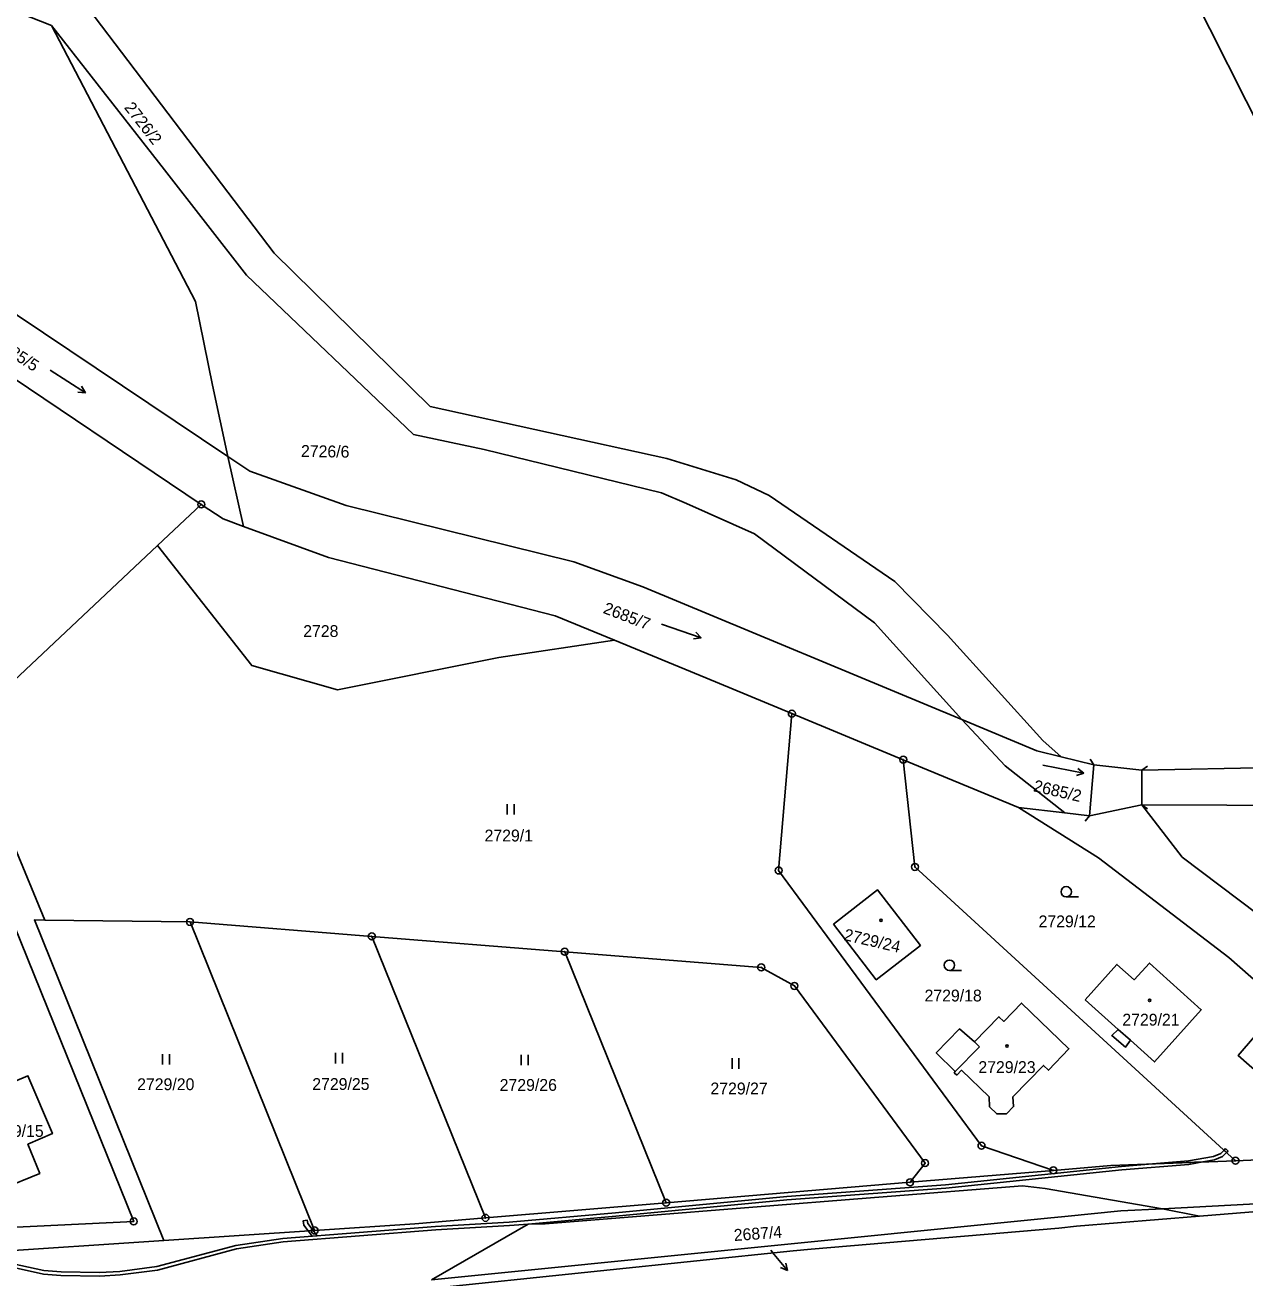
# Model space of a CAD drawing. Extents: x -562167 to -556918, y -1077891 to -1070763.
# Drawn here: x -561602.8 to -561427.7, y -1076310.6 to -1076130.7 of the extents above; entities that cross this region are included whole.
import ezdxf

# ---------------------------------------------------------------- set-up
doc = ezdxf.new("R2010")
doc.units = 0
for name, color, linetype in [('Hranice parcel', 7, 'Continuous'), ('Parcelní čísla', 7, 'Continuous'), ('Pop  PČ popisy', 7, 'Continuous'), ('Vnitřní kresba', 7, 'Continuous'), ('Věcná břemena k části', 7, 'Continuous'), ('Značky bodu BP', 7, 'Continuous'), ('Značky budov', 7, 'Continuous'), ('Značky kultur', 7, 'Continuous')]:
    doc.layers.add(name, color=color, linetype=linetype)

msp = doc.modelspace()

# ---------------------------------------------------------------- linework, layer by layer
at = {"layer": 'Hranice parcel'}
for p, q in [((-561571.48, -1076202.71), (-561573.75, -1076192.66)), ((-561577.54, -1076199.54), (-561583.82, -1076205.45)), ((-561611.5, -1076231.49), (-561583.82, -1076205.45)), ((-561492.75, -1076229.57), (-561494.65, -1076252.1)), ((-561476.76, -1076236.19), (-561492.75, -1076229.57)), ((-561611.5, -1076231.49), (-561599.99, -1076259.22)), ((-561460.21, -1076243.05), (-561476.76, -1076236.19)), ((-561449.38, -1076236.95), (-561454.1, -1076235.78)), ((-561449.38, -1076236.95), (-561450, -1076244.24)), ((-561449.38, -1076236.95), (-561442.49, -1076237.7)), ((-561442.49, -1076237.7), (-561375.18, -1076236.27)), ((-561453.54, -1076243.83), (-561460.21, -1076243.05)), ((-561450, -1076244.24), (-561453.54, -1076243.83)), ((-561442.52, -1076242.68), (-561450, -1076244.24)), ((-561494.65, -1076252.1), (-561465.52, -1076291.6)), ((-561599.99, -1076259.22), (-561579.16, -1076259.48)), ((-561579.16, -1076259.48), (-561553.06, -1076261.56)), ((-561561.27, -1076303.77), (-561579.16, -1076259.48)), ((-561553.06, -1076261.56), (-561525.36, -1076263.76)), ((-561536.74, -1076301.96), (-561553.06, -1076261.56)), ((-561510.8, -1076299.79), (-561525.36, -1076263.76)), ((-561465.52, -1076291.6), (-561455.2, -1076295.14)), ((-561429.05, -1076293.76), (-561402.88, -1076292.75)), ((-561473.63, -1076294.09), (-561475.77, -1076296.86)), ((-561475.77, -1076296.86), (-561455.2, -1076295.14)), ((-561475.77, -1076296.86), (-561510.8, -1076299.79)), ((-561510.8, -1076299.79), (-561536.74, -1076301.96)), ((-561434.2, -1076301.72), (-561451.88, -1076303.16)), ((-561439.54, -1076300.66), (-561434.2, -1076301.72)), ((-561412.9, -1076299.98), (-561434.2, -1076301.72)), ((-561561.27, -1076303.77), (-561582.91, -1076305.21)), ((-561520.21, -1076309.57), (-561546.88, -1076312.35))]:
    msp.add_line(p, q, dxfattribs=at)
for points in [[(-561375.18, -1076236.27), (-561404.09, -1076188.07), (-561456.17, -1076084.78), (-561492.73, -1076003.82), (-561505.41, -1075975.77), (-561525.58, -1075948.34), (-561553.58, -1075909.05)], [(-561454.1, -1076235.78), (-561456.7, -1076233.45), (-561470.39, -1076218.31), (-561477.97, -1076210.6), (-561496.01, -1076198.25), (-561500.73, -1076196.01), (-561510.72, -1076192.96), (-561544.7, -1076185.49), (-561567.06, -1076163.49), (-561595.66, -1076125.84), (-561602.88, -1076123.5), (-561630.58, -1076112.06), (-561664.84, -1076098.05), (-561685.79, -1076089.54), (-561702.62, -1076082.16), (-561707.57, -1076079.44)], [(-561703.43, -1076087.04), (-561686.65, -1076094.27), (-561665.16, -1076103.09), (-561628.85, -1076118.6), (-561608.1, -1076127.25), (-561599.04, -1076130.81)], [(-561599.04, -1076130.81), (-561582.81, -1076151.5), (-561571.03, -1076166.62), (-561547.05, -1076189.5), (-561536.95, -1076191.66), (-561511.46, -1076197.88), (-561507.86, -1076199.43), (-561498.09, -1076203.78), (-561480.9, -1076216.53), (-561468.34, -1076230.44)], [(-561599.04, -1076130.81), (-561578.36, -1076170.43), (-561575.95, -1076182.41), (-561573.75, -1076192.66)], [(-561573.75, -1076192.66), (-561603.99, -1076172.38), (-561621.59, -1076159.92)], [(-561577.54, -1076199.54), (-561609.14, -1076178.33), (-561619.66, -1076170.1)], [(-561468.34, -1076230.44), (-561514.16, -1076211.36), (-561524.03, -1076207.79), (-561556.75, -1076199.71), (-561570.59, -1076194.78), (-561573.75, -1076192.66)], [(-561571.48, -1076202.71), (-561574.41, -1076201.64), (-561577.54, -1076199.54)], [(-561518.21, -1076219.03), (-561526.71, -1076215.56), (-561559.3, -1076207.17), (-561571.48, -1076202.71)], [(-561583.82, -1076205.45), (-561570.29, -1076222.68), (-561557.97, -1076226.14), (-561534.8, -1076221.5), (-561518.21, -1076219.03)], [(-561492.75, -1076229.57), (-561505.12, -1076224.46), (-561518.21, -1076219.03)], [(-561468.34, -1076230.44), (-561462.1, -1076237.08), (-561453.54, -1076243.83)], [(-561454.1, -1076235.78), (-561457.6, -1076234.91), (-561468.34, -1076230.44)], [(-561476.76, -1076236.19), (-561475.08, -1076251.58), (-561429.05, -1076293.76)], [(-560892.63, -1076504.95), (-560992.78, -1076428.54), (-561153.22, -1076306.14), (-561232.09, -1076245.97), (-561245.36, -1076241.41), (-561369.37, -1076242.96), (-561442.52, -1076242.68)], [(-561460.21, -1076243.05), (-561448.7, -1076250.26), (-561430.01, -1076264.57), (-561410.64, -1076281.61), (-561402.88, -1076292.75)], [(-561442.52, -1076242.68), (-561436.7, -1076250.18), (-561420.36, -1076262.53), (-561399, -1076282.72), (-561385.24, -1076297.36)], [(-561486.77, -1076259.82), (-561480.43, -1076254.88), (-561474.3, -1076262.85), (-561480.64, -1076267.78), (-561486.77, -1076259.82)], [(-561605.37, -1076257.6), (-561587.25, -1076302.47), (-561609.08, -1076303.54)], [(-561582.91, -1076305.21), (-561601.49, -1076259.2), (-561599.99, -1076259.22)], [(-561525.36, -1076263.76), (-561497.15, -1076266.01), (-561492.38, -1076268.66), (-561473.63, -1076294.09)], [(-561450.62, -1076270.65), (-561446.07, -1076265.57), (-561443.58, -1076267.79), (-561441.42, -1076265.39), (-561433.97, -1076272.09), (-561440.67, -1076279.57), (-561444.14, -1076276.46), (-561444.87, -1076277.48), (-561446.82, -1076275.77), (-561445.88, -1076274.9), (-561450.62, -1076270.65)], [(-561469.07, -1076281.46), (-561469.43, -1076281.12), (-561469.28, -1076280.96), (-561472.01, -1076278.28), (-561468.66, -1076274.85), (-561466.51, -1076276.69), (-561463.03, -1076273.09), (-561462.31, -1076273.77), (-561459.78, -1076271.12), (-561452.96, -1076277.69), (-561455.92, -1076280.77), (-561456.63, -1076280.08), (-561461, -1076284.61), (-561460.92, -1076285.99), (-561461.94, -1076287.02), (-561463.33, -1076287.03), (-561464.38, -1076286.02), (-561464.42, -1076284.59), (-561468.37, -1076280.76), (-561469.07, -1076281.46)], [(-561421.3, -1076285.04), (-561427.09, -1076280.03), (-561428.69, -1076278.64), (-561423.99, -1076273.22), (-561422.39, -1076274.61), (-561416.61, -1076279.62), (-561421.3, -1076285.04)], [(-561606.14, -1076297.79), (-561607.99, -1076293.39), (-561606.41, -1076292.76), (-561609.81, -1076284.69), (-561602.43, -1076281.55), (-561598.92, -1076289.86), (-561602.43, -1076291.4), (-561600.73, -1076295.58), (-561606.14, -1076297.79)], [(-561455.2, -1076295.14), (-561446.93, -1076294.45), (-561429.05, -1076293.76)], [(-561582.91, -1076305.21), (-561608.88, -1076306.94), (-561618.03, -1076306.28), (-561620.03, -1076306.14), (-561649.21, -1076303.23), (-561675.93, -1076298.21), (-561690.64, -1076297.3)], [(-561439.54, -1076300.66), (-561456.4, -1076297.73), (-561459.65, -1076297.35), (-561480.28, -1076299.01), (-561499.57, -1076300.5), (-561528.15, -1076302.8), (-561530.6, -1076302.86), (-561544.47, -1076310.86)], [(-561439.54, -1076300.66), (-561410.09, -1076299.1), (-561394.03, -1076305.99), (-561392.29, -1076308.08)], [(-561544.47, -1076310.86), (-561456.05, -1076302.02), (-561453.56, -1076301.78), (-561445.5, -1076300.97), (-561439.54, -1076300.66)], [(-561536.74, -1076301.96), (-561546.88, -1076302.81), (-561561.27, -1076303.77)], [(-561451.88, -1076303.16), (-561454.42, -1076303.42), (-561490, -1076306.44), (-561492.55, -1076306.7), (-561520.21, -1076309.57)]]:
    msp.add_lwpolyline(points, dxfattribs=at)
at = {"layer": 'Pop  PČ popisy'}
for p, q in [((-561495.78, -1076306.59), (-561495.27, -1076307.21)), ((-561495.27, -1076307.21), (-561493.38, -1076309.54)), ((-561493.38, -1076309.54), (-561493.62, -1076308.45)), ((-561493.38, -1076309.54), (-561494.4, -1076309.08))]:
    msp.add_line(p, q, dxfattribs=at)
at = {"layer": 'Vnitřní kresba'}
for p, q in [((-561449.92, -1076236.11), (-561449.38, -1076236.95)), ((-561442.52, -1076242.68), (-561442.49, -1076237.7)), ((-561441.68, -1076237.11), (-561442.49, -1076237.7)), ((-561441.69, -1076243.24), (-561442.52, -1076242.68)), ((-561450.66, -1076245), (-561450, -1076244.24)), ((-561445.88, -1076274.9), (-561444.14, -1076276.46)), ((-561469.28, -1076280.96), (-561465.81, -1076277.4)), ((-561465.81, -1076277.4), (-561466.51, -1076276.69))]:
    msp.add_line(p, q, dxfattribs=at)
at = {"layer": 'Věcná břemena k části'}
for points in [[(-561440.95, -1076294.22), (-561433.73, -1076293.94), (-561432.05, -1076293.65), (-561430.9, -1076293.14), (-561430.33, -1076292.58), (-561430.7, -1076292.25), (-561431.18, -1076292.72), (-561432.19, -1076293.17), (-561435.81, -1076293.79)], [(-561430.47, -1076292.02), (-561430.7, -1076292.25), (-561430.33, -1076292.58), (-561430.12, -1076292.38)], [(-561562.82, -1076303), (-561562.18, -1076303.83), (-561561.46, -1076303.78), (-561562.26, -1076302.76), (-561562.32, -1076302.31), (-561562.92, -1076302.4)], [(-561560.89, -1076304.52), (-561561.46, -1076303.78), (-561562.18, -1076303.83), (-561561.6, -1076304.58)]]:
    msp.add_lwpolyline(points, close=True, dxfattribs=at)
msp.add_lwpolyline([(-561604.68, -1076309.06), (-561600.22, -1076310.04), (-561597.7, -1076310.23), (-561592.12, -1076310.31), (-561589.18, -1076310.15), (-561583.82, -1076309.45), (-561572.5, -1076306.42), (-561565.78, -1076305.41), (-561543.87, -1076303.68), (-561533.3, -1076303.08), (-561530.6, -1076302.86), (-561518.03, -1076301.73), (-561493.45, -1076299.38), (-561470.64, -1076297.71), (-561445.38, -1076295.09), (-561435.75, -1076294.29), (-561433.73, -1076293.94), (-561440.95, -1076294.22), (-561445.42, -1076294.59), (-561470.68, -1076297.21), (-561493.49, -1076298.88), (-561518.07, -1076301.23), (-561533.34, -1076302.58), (-561543.91, -1076303.18), (-561565.84, -1076304.91), (-561572.6, -1076305.92), (-561583.92, -1076308.95), (-561589.22, -1076309.65), (-561592.14, -1076309.81), (-561597.68, -1076309.73), (-561600.14, -1076309.54), (-561604.54, -1076308.58)], dxfattribs=at)
at = {"layer": 'Značky bodu BP'}
for centre, radius in [((-561577.54, -1076199.54), 0.5), ((-561577.54, -1076199.54), 0.0303), ((-561492.75, -1076229.57), 0.5), ((-561492.75, -1076229.57), 0.0303), ((-561476.76, -1076236.19), 0.5), ((-561476.76, -1076236.19), 0.0303), ((-561475.08, -1076251.58), 0.5), ((-561494.65, -1076252.1), 0.5), ((-561494.65, -1076252.1), 0.0303), ((-561475.08, -1076251.58), 0.0303), ((-561579.16, -1076259.48), 0.5), ((-561579.16, -1076259.48), 0.0303), ((-561553.06, -1076261.56), 0.5), ((-561553.06, -1076261.56), 0.0303), ((-561525.36, -1076263.76), 0.5), ((-561525.36, -1076263.76), 0.0303), ((-561497.15, -1076266.01), 0.5), ((-561497.15, -1076266.01), 0.0303), ((-561492.38, -1076268.66), 0.5), ((-561492.38, -1076268.66), 0.0303), ((-561465.52, -1076291.6), 0.5), ((-561465.52, -1076291.6), 0.0303), ((-561473.63, -1076294.09), 0.5), ((-561473.63, -1076294.09), 0.0303), ((-561429.05, -1076293.76), 0.5), ((-561429.05, -1076293.76), 0.0303), ((-561475.77, -1076296.86), 0.5), ((-561455.2, -1076295.14), 0.5), ((-561455.2, -1076295.14), 0.0303), ((-561475.77, -1076296.86), 0.0303), ((-561510.8, -1076299.79), 0.5), ((-561510.8, -1076299.79), 0.0303), ((-561536.74, -1076301.96), 0.5), ((-561587.25, -1076302.47), 0.5), ((-561587.25, -1076302.47), 0.0303), ((-561561.27, -1076303.77), 0.5), ((-561536.74, -1076301.96), 0.0303), ((-561561.27, -1076303.77), 0.0303)]:
    msp.add_circle(centre, radius, dxfattribs=at)
at = {"layer": 'Značky budov'}
for centre in [(-561479.95, -1076259.24), (-561441.38, -1076270.74), (-561461.86, -1076277.3)]:
    msp.add_circle(centre, 0.175, dxfattribs=at)
at = {"layer": 'Značky kultur'}
for p, q in [((-561599.23, -1076180.27), (-561594.19, -1076183.54)), ((-561594.19, -1076183.54), (-561594.74, -1076182.59)), ((-561594.19, -1076183.54), (-561595.29, -1076183.43)), ((-561511.45, -1076216.73), (-561505.78, -1076218.68)), ((-561505.78, -1076218.68), (-561506.87, -1076218.84)), ((-561505.78, -1076218.68), (-561506.54, -1076217.89)), ((-561456.72, -1076237), (-561450.83, -1076238.14)), ((-561450.83, -1076238.14), (-561451.89, -1076238.45)), ((-561450.83, -1076238.14), (-561451.69, -1076237.47)), ((-561533.64, -1076244.08), (-561533.64, -1076242.58)), ((-561532.64, -1076244.08), (-561532.64, -1076242.58)), ((-561453.35, -1076255.9), (-561451.6, -1076255.9)), ((-561470.13, -1076266.45), (-561468.38, -1076266.45)), ((-561558.26, -1076279.79), (-561558.26, -1076278.29)), ((-561557.26, -1076279.79), (-561557.26, -1076278.29)), ((-561583.12, -1076279.94), (-561583.12, -1076278.44)), ((-561582.12, -1076279.94), (-561582.12, -1076278.44)), ((-561531.6, -1076280.05), (-561531.6, -1076278.55)), ((-561530.6, -1076280.05), (-561530.6, -1076278.55)), ((-561501.34, -1076280.56), (-561501.34, -1076279.06)), ((-561500.34, -1076280.56), (-561500.34, -1076279.06))]:
    msp.add_line(p, q, dxfattribs=at)
for centre in [(-561453.35, -1076255.15), (-561470.13, -1076265.7)]:
    msp.add_circle(centre, 0.75, dxfattribs=at)

# ---------------------------------------------------------------- texts
at = {"layer": 'Parcelní čísla'}
for s, rotation, p in [('2726/2', 308, (-561588.69, -1076142.6)), ('2685/5', 327, (-561607.41, -1076176.76)), ('2726/6', 359, (-561563.24, -1076192.72)), ('2685/7', 339, (-561519.97, -1076215.1)), ('2685/2', 347, (-561458.17, -1076240.71)), ('2729/24', 347, (-561485.39, -1076262.07)), ('2687/4', 4, (-561501.03, -1076305.29))]:
    msp.add_text(s, height=1.7, rotation=rotation, dxfattribs=at).set_placement(p)
for s, p in [('2728', (-561562.91, -1076218.58)), ('2729/1', (-561536.87, -1076247.93)), ('2729/12', (-561457.33, -1076260.25)), ('2729/18', (-561473.7, -1076270.9)), ('2729/21', (-561445.3, -1076274.36)), ('2729/23', (-561465.97, -1076281.17)), ('2729/20', (-561586.75, -1076283.63)), ('2729/25', (-561561.61, -1076283.6)), ('2729/26', (-561534.7, -1076283.73)), ('2729/27', (-561504.44, -1076284.24)), ('2729/15', (-561608.39, -1076290.34))]:
    msp.add_text(s, height=1.7, dxfattribs=at).set_placement(p)

doc.saveas('drawing.dxf')
